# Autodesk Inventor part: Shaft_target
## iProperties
Created: 2008-06
Part Number: Shaft_target
Document SubType Name: Modeling
Designer: CADCIM
Density: 1 g/cm^3
Author: CADCIM
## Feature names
1. Extrusion1
